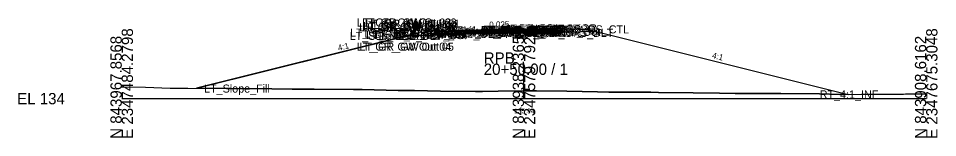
# Model space of a CAD drawing. Extents: x -76 to 2347760, y -10 to 844216.
# Drawn here: x -25.7 to 202.8, y 5490.3 to 5519.9 of the extents above; entities that cross this region are included whole.
import ezdxf

# ---------------------------------------------------------------- set-up
doc = ezdxf.new("R2010")
doc.units = 0
for name, color, linetype in [('Default', 7, 'Continuous'), ('Exist Cross Section Cell', 7, 'Continuous'), ('Exist XS Center Line Elevation Label', 7, 'Continuous'), ('Exist XS Ground Line', 7, 'Continuous'), ('Prop CMT Pvmt Course 1', 7, 'Continuous'), ('Prop CMT Pvmt Course 2', 7, 'Continuous'), ('Prop CMT Pvmt Course 3', 7, 'Continuous'), ('Prop CMT Pvmt Surface', 7, 'Continuous'), ('Prop CMT Pvmt Surface Shoulder', 7, 'Continuous'), ('Prop CMT Shld Paved Course 1', 7, 'Continuous'), ('Prop CMT Shld Paved Course 2', 7, 'Continuous'), ('Prop CMT Shld Paved Course 3', 7, 'Continuous'), ('Prop CMT Slope Grass', 7, 'Continuous'), ('Prop CMT Subgrade Earthwork', 7, 'Continuous'), ('Prop XS Earthwork Shape', 7, 'Continuous'), ('Prop XS SE Text', 7, 'Continuous'), ('Prop XS Side Slope Text', 7, 'Continuous'), ('Scratch_Level_0', 7, 'Continuous')]:
    doc.layers.add(name, color=color, linetype=linetype)

msp = doc.modelspace()

# ---------------------------------------------------------------- linework, layer by layer
at = {"layer": 'Exist Cross Section Cell'}
for p, q in [((100, 5500), (100, 5508.7)), ((0, 5500), (100, 5500)), ((100, 5500), (200, 5500))]:
    msp.add_line(p, q, dxfattribs=at)
at = {"layer": 'Exist XS Ground Line'}
msp.add_lwpolyline([(0, 5502.9), (5.93, 5502.82), (12.06, 5502.6), (16.4, 5502.58), (26.04, 5502.54), (26.87, 5502.55), (27.24, 5502.54), (37.34, 5502.4), (42.41, 5502.33), (47.81, 5502.31), (57.59, 5502.26), (58.28, 5502.25), (59.8, 5502.24), (68.75, 5502.06), (72.77, 5502.03), (79.22, 5501.83), (87.94, 5501.76), (89.69, 5501.77), (93.57, 5501.82), (100.16, 5501.94), (103.12, 5501.94), (110.63, 5501.89), (118.3, 5501.67), (121.1, 5501.6), (127.33, 5501.59), (131.57, 5501.58), (133.47, 5501.55), (142.04, 5501.48), (148.65, 5501.36), (152.51, 5501.25), (161.09, 5501.29), (162.53, 5501.3), (162.98, 5501.3), (163.83, 5501.27), (173.45, 5501.15), (178.51, 5500.99), (183.92, 5501.13), (194.39, 5501.14), (194.85, 5501.15), (200, 5501.18)], dxfattribs=at)
at = {"layer": 'Prop CMT Pvmt Course 1'}
for p, q in [((100, 5517.29), (88, 5516.99)), ((88, 5516.74), (100, 5517.04)), ((88, 5516.99), (88, 5516.74)), ((100, 5517.29), (104, 5517.39)), ((100, 5517.04), (100, 5517.29)), ((100, 5517.04), (100, 5517.29)), ((100, 5517.04), (100, 5517.16)), ((100, 5517.16), (100, 5517.16)), ((100, 5517.16), (100, 5517.04)), ((100, 5517.04), (100, 5517.16)), ((100, 5517.16), (100, 5517.16)), ((100, 5517.16), (100, 5517.04)), ((104, 5517.14), (100, 5517.04)), ((100, 5517.04), (100, 5517.04)), ((100, 5517.04), (100, 5517.04)), ((104, 5517.39), (104, 5517.14))]:
    msp.add_line(p, q, dxfattribs=at)
at = {"layer": 'Prop CMT Pvmt Course 2'}
for p, q in [((100, 5517.04), (88, 5516.74)), ((100, 5517.04), (104, 5517.14)), ((100, 5516.7), (100, 5517.04)), ((100, 5516.7), (100, 5517.04)), ((104, 5516.8), (100, 5516.7)), ((104, 5517.14), (104, 5516.8)), ((88, 5516.74), (88, 5516.4)), ((88, 5516.4), (100, 5516.7))]:
    msp.add_line(p, q, dxfattribs=at)
at = {"layer": 'Prop CMT Pvmt Course 3'}
for p, q in [((100, 5516.7), (104, 5516.8)), ((104, 5516.8), (104, 5516.47)), ((100, 5516.7), (88, 5516.4)), ((88, 5516.4), (88, 5516.07)), ((88, 5516.07), (100, 5516.37)), ((100, 5516.37), (100, 5516.7)), ((100, 5516.37), (100, 5516.7)), ((104, 5516.47), (100, 5516.37))]:
    msp.add_line(p, q, dxfattribs=at)
at = {"layer": 'Prop CMT Pvmt Surface'}
for q in [(88, 5516.99), (104, 5517.39)]:
    msp.add_line((100, 5517.29), q, dxfattribs=at)
at = {"layer": 'Prop CMT Pvmt Surface Shoulder'}
for p, q in [((88, 5516.99), (78, 5516.74)), ((104, 5517.39), (108, 5517.49))]:
    msp.add_line(p, q, dxfattribs=at)
at = {"layer": 'Prop CMT Shld Paved Course 1'}
for p, q in [((88, 5516.99), (78, 5516.74)), ((88, 5516.74), (88, 5516.99)), ((104, 5517.39), (108, 5517.49)), ((104, 5517.14), (104, 5517.39)), ((108.24, 5517.24), (104, 5517.14)), ((108, 5517.49), (108.24, 5517.24)), ((78, 5516.74), (77.74, 5516.48)), ((77.74, 5516.48), (88, 5516.74))]:
    msp.add_line(p, q, dxfattribs=at)
at = {"layer": 'Prop CMT Shld Paved Course 2'}
for p, q in [((104, 5517.14), (108.24, 5517.24)), ((104, 5516.8), (104, 5517.14)), ((108.57, 5516.92), (104, 5516.8)), ((108.24, 5517.24), (108.57, 5516.92)), ((77.74, 5516.48), (77.4, 5516.14)), ((77.4, 5516.14), (88, 5516.4)), ((88, 5516.74), (77.74, 5516.48)), ((88, 5516.4), (88, 5516.74))]:
    msp.add_line(p, q, dxfattribs=at)
at = {"layer": 'Prop CMT Shld Paved Course 3'}
for p, q in [((104, 5516.8), (108.57, 5516.92)), ((104, 5516.47), (104, 5516.8)), ((108.57, 5516.92), (109.07, 5516.93)), ((109.07, 5516.93), (109.39, 5516.61)), ((76.9, 5516.13), (76.56, 5515.79)), ((76.56, 5515.79), (88, 5516.07)), ((77.4, 5516.14), (76.9, 5516.13)), ((88, 5516.4), (77.4, 5516.14)), ((88, 5516.07), (88, 5516.4)), ((109.39, 5516.61), (104, 5516.47))]:
    msp.add_line(p, q, dxfattribs=at)
at = {"layer": 'Prop CMT Slope Grass'}
for p, q in [((108, 5517.49), (116, 5517.21)), ((116, 5517.21), (180.64, 5501.05)), ((74, 5516.42), (18.6, 5502.57)), ((78, 5516.74), (74, 5516.42))]:
    msp.add_line(p, q, dxfattribs=at)
at = {"layer": 'Prop CMT Subgrade Earthwork'}
for p, q in [((104, 5516.47), (117.59, 5516.81)), ((76.56, 5515.79), (70.9, 5515.64)), ((88, 5516.07), (76.56, 5515.79)), ((100, 5516.37), (88, 5516.07)), ((100, 5516.37), (104, 5516.47))]:
    msp.add_line(p, q, dxfattribs=at)
at = {"layer": 'Prop XS Earthwork Shape'}
msp.add_lwpolyline([(100, 5516.37), (104, 5516.47), (117.59, 5516.81), (180.64, 5501.05), (178.51, 5500.99), (173.45, 5501.15), (163.83, 5501.27), (162.98, 5501.3), (162.53, 5501.3), (161.09, 5501.29), (152.51, 5501.25), (148.65, 5501.36), (142.04, 5501.48), (133.47, 5501.55), (131.57, 5501.58), (127.33, 5501.59), (121.1, 5501.6), (118.3, 5501.67), (110.63, 5501.89), (103.12, 5501.94), (100.16, 5501.94), (93.57, 5501.82), (89.69, 5501.77), (87.94, 5501.76), (79.22, 5501.83), (72.77, 5502.03), (68.75, 5502.06), (59.8, 5502.24), (58.28, 5502.25), (57.59, 5502.26), (47.81, 5502.31), (42.41, 5502.33), (37.34, 5502.4), (27.24, 5502.54), (26.87, 5502.55), (26.04, 5502.54), (18.6, 5502.57), (70.9, 5515.64), (76.56, 5515.79), (88, 5516.07)], close=True, dxfattribs=at)

# ---------------------------------------------------------------- texts
at = {"layer": 'Default'}
msp.add_text('-', height=0.0001, dxfattribs=at).set_placement((0, 5500))
at = {"layer": 'Exist Cross Section Cell'}
for s, p in [('E 2347484.2798', (2.8, 5490)), ('E 2347579.7923', (102.8, 5490)), ('E 2347675.3048', (202.8, 5490)), ('N 843967.8568', (0, 5490)), ('N 843938.2365', (100, 5490)), ('N 843908.6162', (200, 5490))]:
    msp.add_text(s, height=2.8, rotation=90, dxfattribs=at).set_placement(p)
for s, p in [('RPB', (90, 5508.7)), ('20+50.00 / 1', (90, 5505.9)), ('EL 134', (-26, 5498.6))]:
    msp.add_text(s, height=2.8, dxfattribs=at).set_placement(p)
at = {"layer": 'Exist XS Center Line Elevation Label'}
msp.add_text('135.94', height=1.2, dxfattribs=at).set_placement((97.55, 5496.34))
at = {"layer": 'Prop XS SE Text'}
msp.add_text('0.025', height=1.5, rotation=1.4321, dxfattribs=at).set_placement((91.38, 5517.64))
at = {"layer": 'Prop XS Side Slope Text'}
for rotation, p in [(14.0362, (53.93, 5511.85)), (345.9638, (146.64, 5510.1))]:
    msp.add_text('4:1', height=1.5, rotation=rotation, dxfattribs=at).set_placement(p)
at = {"layer": 'Scratch_Level_0'}
for s, p in [('LT_GR_GW Out 03', (58.43, 5517.92)), ('LT_GR_GW Out 02', (59.77, 5517.92)), ('LT_GR_GW Out 09', (59.77, 5517.33)), ('LT_GR_GW Out 08', (60.04, 5517.04)), ('LT_GR_GW Out 01', (60.6, 5517.63)), ('LT_GS_OS_GR_Face_GW', (56.75, 5515.42)), ('LT_GR_GW Out 06', (59.05, 5516.75)), ('LT_GR_GW Out 07', (59.77, 5516.75)), ('LT_GS_OS_CTL', (60.36, 5515.18)), ('LT_Sub_Trench_Out', (60.76, 5514.79)), ('LT_PS3_Shelf_Out', (62.89, 5515.13)), ('LT_PS3_OEOP', (67.64, 5515.14)), ('LT_PS2_OEOP', (67.98, 5515.48)), ('LT_PS1_OEOP', (68.8, 5515.74)), ('LT_Sub_OEOT', (78.08, 5515.07)), ('LT_PV2_OEOT', (78.17, 5515.74)), ('LT_PV3_OEOT', (78.17, 5515.4)), ('LT_PV1_OEOT', (78.74, 5515.99)), ('RT_Sub_OEEOP', (89.17, 5515.37)), ('LT_Sub_OEEOP', (89.21, 5515.37)), ('RT_PV2_OEEOP', (89.26, 5516.04)), ('RT_PV3_OEEOP', (89.26, 5515.7)), ('LT_PV2_OEEOP', (89.31, 5516.04)), ('LT_PV3_OEEOP', (89.31, 5515.7)), ('RT_PV1_OEEOP', (89.83, 5516.16)), ('LT_PV1_OEEOP', (89.87, 5516.16)), ('RT_PV2_IEEOP', (89.91, 5516.04)), ('LT_PV2_IEEOP', (89.95, 5516.04)), ('RT_PV1_IEEOP', (90.47, 5516.16)), ('LT_PV1_IEEOP', (90.52, 5516.16)), ('RT_Sub_Trench_Out', (93.55, 5515.61)), ('PV2_PGL', (93.91, 5516.04)), ('RT_Sub_OEOT', (94.03, 5515.47)), ('RT_PV2_OEOT', (94.13, 5516.14)), ('RT_PV3_OEOT', (94.13, 5515.8)), ('PV1_PGL', (94.47, 5516.29)), ('RT_PV1_OEOT', (94.69, 5516.39)), ('RT_PS3_Shelf_Out', (95.01, 5515.93)), ('RT_PS2_OEOP', (98.43, 5516.24)), ('RT_Sub_OSS_DLT', (98.75, 5515.35)), ('RT_PS1_OEOP', (98.76, 5516.49)), ('RT_PS3_OEOP', (98.76, 5515.92)), ('RT_GS_OS_CTL', (105.32, 5516.21)), ('LT_Sub_OSS_DLT', (56.67, 5514.6)), ('LT_GR_GW Out 04', (58.43, 5511.92)), ('LT_GR_GW Out 05', (59.1, 5511.92)), ('LT_Slope_Fill', (20.48, 5501.5)), ('RT_4:1_INF', (173.53, 5500.05))]:
    msp.add_text(s, height=2, dxfattribs=at).set_placement(p)

doc.saveas('drawing.dxf')
